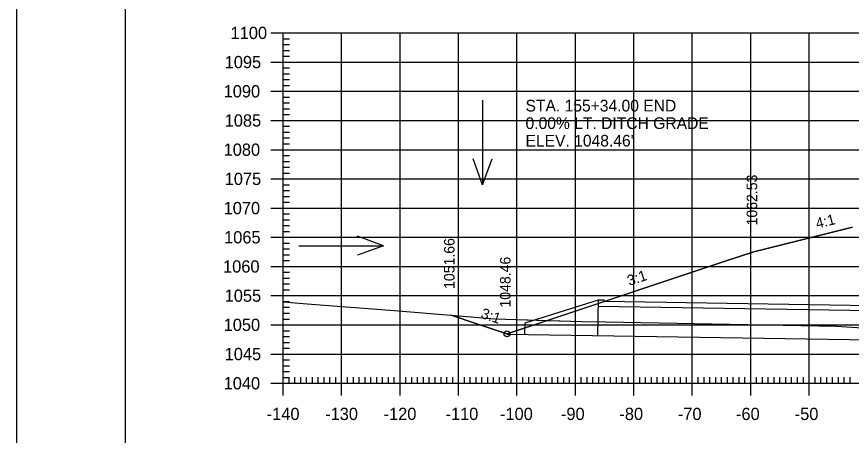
# Model space of a CAD drawing. Extents: x 1322838 to 1324533, y 339903 to 351025.
# Drawn here: x 1323450 to 1323592.8, y 344925.2 to 344996.9 of the extents above; entities that cross this region are included whole.
import ezdxf

# ---------------------------------------------------------------- set-up
doc = ezdxf.new("R2010")
doc.units = 0
for name, color, linetype in [('R_Axis', 7, 'Continuous'), ('R_Axis Annot', 7, 'Continuous'), ('R_Border', 7, 'Continuous'), ('R_Drive', 7, 'Continuous'), ('R_Exist Surface', 7, 'Continuous'), ('R_Fin Surface', 7, 'Continuous'), ('R_Grid', 7, 'Continuous'), ('R_No Plot', 7, 'Continuous'), ('R_Water', 7, 'Continuous'), ('R_Water Annot', 7, 'Continuous'), ('R_Xsect Elev', 7, 'Continuous'), ('R_Xsect Slope', 7, 'Continuous')]:
    doc.layers.add(name, color=color, linetype=linetype)

msp = doc.modelspace()

# ---------------------------------------------------------------- linework, layer by layer
at = {"layer": 'R_Axis'}
for p, q in [((1323493.48, 344994.14), (1323497.68, 344994.14)), ((1323495.58, 344934.14), (1323495.58, 344994.14)), ((1323495.58, 344993.14), (1323496.63, 344993.14)), ((1323495.58, 344992.14), (1323496.63, 344992.14)), ((1323495.58, 344991.14), (1323496.63, 344991.14)), ((1323495.58, 344990.14), (1323496.63, 344990.14)), ((1323493.48, 344989.14), (1323497.68, 344989.14)), ((1323495.58, 344988.14), (1323496.63, 344988.14)), ((1323495.58, 344987.14), (1323496.63, 344987.14)), ((1323495.58, 344986.14), (1323496.63, 344986.14)), ((1323495.58, 344985.14), (1323496.63, 344985.14)), ((1323493.48, 344984.14), (1323497.68, 344984.14)), ((1323495.58, 344983.14), (1323496.63, 344983.14)), ((1323495.58, 344982.14), (1323496.63, 344982.14)), ((1323495.58, 344981.14), (1323496.63, 344981.14)), ((1323495.58, 344980.14), (1323496.63, 344980.14)), ((1323493.48, 344979.14), (1323497.68, 344979.14)), ((1323495.58, 344978.14), (1323496.63, 344978.14)), ((1323495.58, 344977.14), (1323496.63, 344977.14)), ((1323495.58, 344976.14), (1323496.63, 344976.14)), ((1323495.58, 344975.14), (1323496.63, 344975.14)), ((1323493.48, 344974.14), (1323497.68, 344974.14)), ((1323495.58, 344973.14), (1323496.63, 344973.14)), ((1323495.58, 344972.14), (1323496.63, 344972.14)), ((1323495.58, 344971.14), (1323496.63, 344971.14)), ((1323495.58, 344970.14), (1323496.63, 344970.14)), ((1323493.48, 344969.14), (1323497.68, 344969.14)), ((1323495.58, 344968.14), (1323496.63, 344968.14)), ((1323495.58, 344967.14), (1323496.63, 344967.14)), ((1323495.58, 344966.14), (1323496.63, 344966.14)), ((1323495.58, 344965.14), (1323496.63, 344965.14)), ((1323493.48, 344964.14), (1323497.68, 344964.14)), ((1323495.58, 344963.14), (1323496.63, 344963.14)), ((1323495.58, 344962.14), (1323496.63, 344962.14)), ((1323495.58, 344961.14), (1323496.63, 344961.14)), ((1323495.58, 344960.14), (1323496.63, 344960.14)), ((1323493.48, 344959.14), (1323497.68, 344959.14)), ((1323495.58, 344958.14), (1323496.63, 344958.14)), ((1323495.58, 344957.14), (1323496.63, 344957.14)), ((1323495.58, 344956.14), (1323496.63, 344956.14)), ((1323495.58, 344955.14), (1323496.63, 344955.14)), ((1323493.48, 344954.14), (1323497.68, 344954.14)), ((1323495.58, 344953.14), (1323496.63, 344953.14)), ((1323495.58, 344952.14), (1323496.63, 344952.14)), ((1323495.58, 344951.14), (1323496.63, 344951.14)), ((1323495.58, 344950.14), (1323496.63, 344950.14)), ((1323493.48, 344949.14), (1323497.68, 344949.14)), ((1323495.58, 344948.14), (1323496.63, 344948.14)), ((1323495.58, 344947.14), (1323496.63, 344947.14)), ((1323495.58, 344946.14), (1323496.63, 344946.14)), ((1323495.58, 344945.14), (1323496.63, 344945.14)), ((1323493.48, 344944.14), (1323497.68, 344944.14)), ((1323495.58, 344943.14), (1323496.63, 344943.14)), ((1323495.58, 344942.14), (1323496.63, 344942.14)), ((1323495.58, 344941.14), (1323496.63, 344941.14)), ((1323495.58, 344940.14), (1323496.63, 344940.14)), ((1323493.48, 344939.14), (1323497.68, 344939.14)), ((1323495.58, 344938.14), (1323496.63, 344938.14)), ((1323495.58, 344937.14), (1323496.63, 344937.14)), ((1323495.58, 344932.04), (1323495.58, 344936.24)), ((1323495.58, 344936.14), (1323496.63, 344936.14)), ((1323495.58, 344935.14), (1323496.63, 344935.14)), ((1323496.58, 344934.14), (1323496.58, 344935.19)), ((1323497.58, 344934.14), (1323497.58, 344935.19)), ((1323498.58, 344934.14), (1323498.58, 344935.19)), ((1323499.58, 344934.14), (1323499.58, 344935.19)), ((1323500.58, 344934.14), (1323500.58, 344935.19)), ((1323501.58, 344934.14), (1323501.58, 344935.19)), ((1323502.58, 344934.14), (1323502.58, 344935.19)), ((1323503.58, 344934.14), (1323503.58, 344935.19)), ((1323504.58, 344934.14), (1323504.58, 344935.19)), ((1323505.58, 344932.04), (1323505.58, 344936.24)), ((1323506.58, 344934.14), (1323506.58, 344935.19)), ((1323507.58, 344934.14), (1323507.58, 344935.19)), ((1323508.58, 344934.14), (1323508.58, 344935.19)), ((1323509.58, 344934.14), (1323509.58, 344935.19)), ((1323510.58, 344934.14), (1323510.58, 344935.19)), ((1323511.58, 344934.14), (1323511.58, 344935.19)), ((1323512.58, 344934.14), (1323512.58, 344935.19)), ((1323513.58, 344934.14), (1323513.58, 344935.19)), ((1323514.58, 344934.14), (1323514.58, 344935.19)), ((1323515.58, 344932.04), (1323515.58, 344936.24)), ((1323516.58, 344934.14), (1323516.58, 344935.19)), ((1323517.58, 344934.14), (1323517.58, 344935.19)), ((1323518.58, 344934.14), (1323518.58, 344935.19)), ((1323519.58, 344934.14), (1323519.58, 344935.19)), ((1323520.58, 344934.14), (1323520.58, 344935.19)), ((1323521.58, 344934.14), (1323521.58, 344935.19)), ((1323522.58, 344934.14), (1323522.58, 344935.19)), ((1323523.58, 344934.14), (1323523.58, 344935.19)), ((1323524.58, 344934.14), (1323524.58, 344935.19)), ((1323525.58, 344932.04), (1323525.58, 344936.24)), ((1323526.58, 344934.14), (1323526.58, 344935.19)), ((1323527.58, 344934.14), (1323527.58, 344935.19)), ((1323528.58, 344934.14), (1323528.58, 344935.19)), ((1323529.58, 344934.14), (1323529.58, 344935.19)), ((1323530.58, 344934.14), (1323530.58, 344935.19)), ((1323531.58, 344934.14), (1323531.58, 344935.19)), ((1323532.58, 344934.14), (1323532.58, 344935.19)), ((1323533.58, 344934.14), (1323533.58, 344935.19)), ((1323534.58, 344934.14), (1323534.58, 344935.19)), ((1323535.58, 344932.04), (1323535.58, 344936.24)), ((1323536.58, 344934.14), (1323536.58, 344935.19)), ((1323537.58, 344934.14), (1323537.58, 344935.19)), ((1323538.58, 344934.14), (1323538.58, 344935.19)), ((1323539.58, 344934.14), (1323539.58, 344935.19)), ((1323540.58, 344934.14), (1323540.58, 344935.19)), ((1323541.58, 344934.14), (1323541.58, 344935.19)), ((1323542.58, 344934.14), (1323542.58, 344935.19)), ((1323543.58, 344934.14), (1323543.58, 344935.19)), ((1323544.58, 344934.14), (1323544.58, 344935.19)), ((1323545.58, 344932.04), (1323545.58, 344936.24)), ((1323546.58, 344934.14), (1323546.58, 344935.19)), ((1323547.58, 344934.14), (1323547.58, 344935.19)), ((1323548.58, 344934.14), (1323548.58, 344935.19)), ((1323549.58, 344934.14), (1323549.58, 344935.19)), ((1323550.58, 344934.14), (1323550.58, 344935.19)), ((1323551.58, 344934.14), (1323551.58, 344935.19)), ((1323552.58, 344934.14), (1323552.58, 344935.19)), ((1323553.58, 344934.14), (1323553.58, 344935.19)), ((1323554.58, 344934.14), (1323554.58, 344935.19)), ((1323555.58, 344932.04), (1323555.58, 344936.24)), ((1323556.58, 344934.14), (1323556.58, 344935.19)), ((1323557.58, 344934.14), (1323557.58, 344935.19)), ((1323558.58, 344934.14), (1323558.58, 344935.19)), ((1323559.58, 344934.14), (1323559.58, 344935.19)), ((1323560.58, 344934.14), (1323560.58, 344935.19)), ((1323561.58, 344934.14), (1323561.58, 344935.19)), ((1323562.58, 344934.14), (1323562.58, 344935.19)), ((1323563.58, 344934.14), (1323563.58, 344935.19)), ((1323564.58, 344934.14), (1323564.58, 344935.19)), ((1323565.58, 344932.04), (1323565.58, 344936.24)), ((1323566.58, 344934.14), (1323566.58, 344935.19)), ((1323567.58, 344934.14), (1323567.58, 344935.19)), ((1323568.58, 344934.14), (1323568.58, 344935.19)), ((1323569.58, 344934.14), (1323569.58, 344935.19)), ((1323570.58, 344934.14), (1323570.58, 344935.19)), ((1323571.58, 344934.14), (1323571.58, 344935.19)), ((1323572.58, 344934.14), (1323572.58, 344935.19)), ((1323573.58, 344934.14), (1323573.58, 344935.19)), ((1323574.58, 344934.14), (1323574.58, 344935.19)), ((1323575.58, 344932.04), (1323575.58, 344936.24)), ((1323576.58, 344934.14), (1323576.58, 344935.19)), ((1323577.58, 344934.14), (1323577.58, 344935.19)), ((1323578.58, 344934.14), (1323578.58, 344935.19)), ((1323579.58, 344934.14), (1323579.58, 344935.19)), ((1323580.58, 344934.14), (1323580.58, 344935.19)), ((1323581.58, 344934.14), (1323581.58, 344935.19)), ((1323582.58, 344934.14), (1323582.58, 344935.19)), ((1323583.58, 344934.14), (1323583.58, 344935.19)), ((1323584.58, 344934.14), (1323584.58, 344935.19)), ((1323585.58, 344932.04), (1323585.58, 344936.24)), ((1323586.58, 344934.14), (1323586.58, 344935.19)), ((1323587.58, 344934.14), (1323587.58, 344935.19)), ((1323588.58, 344934.14), (1323588.58, 344935.19)), ((1323589.58, 344934.14), (1323589.58, 344935.19)), ((1323590.58, 344934.14), (1323590.58, 344935.19)), ((1323591.58, 344934.14), (1323591.58, 344935.19)), ((1323592.58, 344934.14), (1323592.58, 344935.19)), ((1323493.48, 344934.14), (1323497.68, 344934.14)), ((1323495.58, 344934.14), (1323915.58, 344934.14))]:
    msp.add_line(p, q, dxfattribs=at)
at = {"layer": 'R_Border'}
msp.add_line((1323468.58, 344830.14), (1323468.58, 345138.33), dxfattribs=at)
at = {"layer": 'R_Exist Surface'}
msp.add_lwpolyline([(1323495.58, 344948.06), (1323499.66, 344947.73), (1323515.28, 344946.55), (1323531.78, 344945.16), (1323546.68, 344944.73), (1323550.76, 344944.68), (1323590.26, 344943.92), (1323596.45, 344943.49)], dxfattribs=at)
at = {"layer": 'R_Fin Surface'}
msp.add_lwpolyline([(1323524.29, 344945.79), (1323528.72, 344944.32), (1323533.87, 344942.6), (1323533.88, 344942.6), (1323533.88, 344942.6), (1323571.4, 344955.11), (1323576.08, 344956.67), (1323576.09, 344956.67), (1323592.99, 344960.89)], dxfattribs=at)
at = {"layer": 'R_Grid'}
for p, q in [((1323495.58, 344994.14), (1323915.58, 344994.14)), ((1323495.58, 344934.14), (1323495.58, 344994.14)), ((1323505.58, 344934.14), (1323505.58, 344994.14)), ((1323515.58, 344934.14), (1323515.58, 344994.14)), ((1323525.58, 344934.14), (1323525.58, 344994.14)), ((1323535.58, 344934.14), (1323535.58, 344994.14)), ((1323545.58, 344934.14), (1323545.58, 344994.14)), ((1323555.58, 344934.14), (1323555.58, 344994.14)), ((1323565.58, 344934.14), (1323565.58, 344994.14)), ((1323575.58, 344934.14), (1323575.58, 344994.14)), ((1323585.58, 344934.14), (1323585.58, 344994.14)), ((1323495.58, 344989.14), (1323915.58, 344989.14)), ((1323495.58, 344984.14), (1323915.58, 344984.14)), ((1323495.58, 344979.14), (1323915.58, 344979.14)), ((1323495.58, 344974.14), (1323915.58, 344974.14)), ((1323495.58, 344969.14), (1323915.58, 344969.14)), ((1323495.58, 344964.14), (1323915.58, 344964.14)), ((1323495.58, 344959.14), (1323915.58, 344959.14)), ((1323495.58, 344954.14), (1323915.58, 344954.14)), ((1323495.58, 344949.14), (1323915.58, 344949.14)), ((1323495.58, 344944.14), (1323915.58, 344944.14)), ((1323495.58, 344939.14), (1323915.58, 344939.14)), ((1323495.58, 344934.14), (1323915.58, 344934.14))]:
    msp.add_line(p, q, dxfattribs=at)
at = {"layer": 'R_No Plot'}
for points in [[(1323449.97, 345144.17), (1323949.98, 345144.17), (1323949.98, 344824.16), (1323449.97, 344824.16)], [(1323819.46, 345138.33), (1323848.89, 345138.33), (1323848.89, 345123.51), (1323873.06, 345123.51), (1323907.86, 345123.51), (1323907.86, 345074.5), (1323942.67, 345074.5), (1323942.85, 344830.14), (1323468.58, 344830.14), (1323468.58, 345138.33)], [(1323524.29, 344945.79), (1323531.78, 344945.16), (1323540.79, 344944.9), (1323533.88, 344942.6), (1323533.88, 344942.6), (1323533.87, 344942.6), (1323528.72, 344944.32)]]:
    msp.add_lwpolyline(points, close=True, dxfattribs=at)
msp.add_lwpolyline([(1323592.99, 344960.89), (1323576.09, 344956.67), (1323576.08, 344956.67), (1323571.4, 344955.11), (1323540.79, 344944.9), (1323546.68, 344944.73), (1323550.76, 344944.68), (1323590.26, 344943.92), (1323596.45, 344943.49)], dxfattribs=at)
msp.add_circle((1323533.87, 344942.6), 0.5, dxfattribs=at)
at = {"layer": 'R_Water'}
for p, q in [((1323549.47, 344948.39), (1323536.91, 344944.42)), ((1323549.47, 344948.39), (1323549.38, 344942.27)), ((1323550.47, 344948.38), (1323549.47, 344948.39)), ((1323550.47, 344948.38), (1323550.47, 344948.13)), ((1323674.32, 344946.19), (1323550.47, 344948.13)), ((1323674.3, 344945.32), (1323549.45, 344947.27)), ((1323536.91, 344944.42), (1323536.88, 344942.47)), ((1323674.93, 344940.31), (1323533.87, 344942.51))]:
    msp.add_line(p, q, dxfattribs=at)
at = {"layer": 'R_Water Annot'}
for p, q in [((1323529.7, 344982.6), (1323529.7, 344968.12)), ((1323529.7, 344968.12), (1323528.09, 344972.55)), ((1323529.7, 344968.12), (1323531.32, 344972.55)), ((1323512.71, 344957.68), (1323508.28, 344959.3)), ((1323498.23, 344957.68), (1323512.71, 344957.68)), ((1323512.71, 344957.68), (1323508.28, 344956.07))]:
    msp.add_line(p, q, dxfattribs=at)

# ---------------------------------------------------------------- texts
at = {"layer": 'R_Axis Annot'}
for s, p in [('1100', (1323486.57, 344993.09)), ('1095', (1323485.56, 344988.09)), ('1090', (1323485.38, 344983.09)), ('1085', (1323485.56, 344978.09)), ('1080', (1323485.38, 344973.09)), ('1075', (1323485.56, 344968.09)), ('1070', (1323485.38, 344963.09)), ('1065', (1323485.46, 344958.09)), ('1060', (1323485.28, 344953.09)), ('1055', (1323485.56, 344948.09)), ('1050', (1323485.38, 344943.09)), ('1045', (1323485.56, 344938.09)), ('1040', (1323485.38, 344933.09)), ('-140', (1323492.75, 344927.84)), ('-130', (1323502.75, 344927.84)), ('-120', (1323512.75, 344927.84)), ('-110', (1323523.34, 344927.84)), ('-100', (1323532.67, 344927.84)), ('-90', (1323543.1, 344927.84)), ('-80', (1323553.1, 344927.84)), ('-70', (1323563.1, 344927.84)), ('-60', (1323573.05, 344927.84)), ('-50', (1323583.1, 344927.84))]:
    msp.add_text(s, height=2.1, dxfattribs=at).set_placement(p)
at = {"layer": 'R_Drive'}
for s, p in [('STA. 155+34.00 END', (1323537.04, 344980.68)), ('0.00% LT. DITCH GRADE', (1323537.04, 344977.68)), ("ELEV. 1048.46'", (1323537.04, 344974.68))]:
    msp.add_text(s, height=1.9999, dxfattribs=at).set_placement(p)
at = {"layer": 'R_Xsect Elev'}
for s, p in [('1062.53', (1323576.68, 344961.17)), ('1051.66', (1323524.89, 344950.29)), ('1048.46', (1323534.47, 344947.1))]:
    msp.add_text(s, height=1.8, rotation=90, dxfattribs=at).set_placement(p)
at = {"layer": 'R_Xsect Slope'}
for s, rotation, p in [('4:1', 14.0363, (1323586.94, 344960.6)), ('3:1', 18.4349, (1323554.79, 344950.8)), ('3:1', 341.564, (1323529.27, 344945.36))]:
    msp.add_text(s, height=1.8, rotation=rotation, dxfattribs=at).set_placement(p)

doc.saveas('drawing.dxf')
